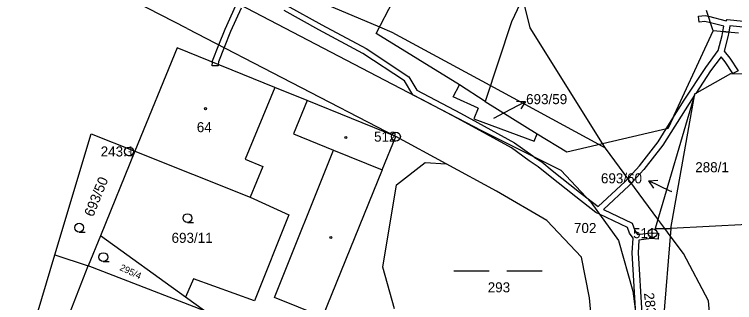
# Model space of a CAD drawing. Extents: x -747333 to -745433, y -1133152 to -1130600.
# Drawn here: x -746346.5 to -746224.7, y -1132134.3 to -1132085.5 of the extents above; entities that cross this region are included whole.
import ezdxf

# ---------------------------------------------------------------- set-up
doc = ezdxf.new("R2010")
doc.units = 0
for name, color, linetype in [('Vrstva 1', 7, 'Continuous'), ('Vrstva 16', 7, 'Continuous'), ('Vrstva 17', 7, 'Continuous'), ('Vrstva 18', 7, 'Continuous'), ('Vrstva 19', 7, 'Continuous'), ('Vrstva 24', 7, 'Continuous'), ('Vrstva 25', 7, 'Continuous'), ('Vrstva 3', 7, 'Continuous'), ('Vrstva 30', 7, 'Continuous'), ('Vrstva 37', 7, 'Continuous'), ('Vrstva 4', 7, 'Continuous'), ('Vrstva 52', 7, 'Continuous'), ('Vrstva 6', 7, 'Continuous')]:
    doc.layers.add(name, color=color, linetype=linetype)

msp = doc.modelspace()

# ---------------------------------------------------------------- linework, layer by layer
at = {"layer": 'Vrstva 1'}
msp.add_line((-746338.7, -1132140.02), (-746334.03, -1132128.06), dxfattribs=at)
for points in [[(-746242.88, -1132045.31), (-746262.42, -1132086.72)], [(-746317.29, -1132087.85), (-746364.32, -1132063.67)], [(-746282.49, -1132097.32), (-746324.12, -1132075.54)], [(-746285.29, -1132088.71), (-746282.45, -1132083.18)], [(-746228.31, -1132088.24), (-746229.39, -1132084.77)], [(-746262.42, -1132086.72), (-746266.88, -1132100.2)], [(-746317.29, -1132087.85), (-746281.98, -1132106.18)], [(-746271.22, -1132097.41), (-746285.29, -1132088.71)], [(-746235.88, -1132104.76), (-746228.31, -1132088.24)], [(-746223.98, -1132088.61), (-746228.31, -1132088.24)], [(-746318.98, -1132091.11), (-746326.13, -1132108.66)], [(-746302.49, -1132097.83), (-746318.98, -1132091.11)], [(-746231.38, -1132098.93), (-746225.32, -1132095.47)], [(-746225.32, -1132095.47), (-746214.11, -1132095.55)], [(-746296.99, -1132100.07), (-746302.49, -1132097.83)], [(-746267.43, -1132105.17), (-746282.49, -1132097.32)], [(-746266.88, -1132100.2), (-746271.22, -1132097.41)], [(-746235.45, -1132121.74), (-746231.38, -1132098.93)], [(-746281.98, -1132106.18), (-746296.99, -1132100.07)], [(-746266.88, -1132100.2), (-746258.07, -1132105.71)], [(-746254.03, -1132111.91), (-746267.43, -1132105.17)], [(-746253.04, -1132108.76), (-746235.88, -1132104.76)], [(-746339.72, -1132126.2), (-746333.57, -1132105.7), (-746326.13, -1132108.66)], [(-746284.28, -1132111.82), (-746281.98, -1132106.18)], [(-746273.47, -1132110.79), (-746281.98, -1132106.18)], [(-746258.07, -1132105.71), (-746253.04, -1132108.76)], [(-746326.13, -1132108.66), (-746331.96, -1132122.97)], [(-746326.13, -1132108.66), (-746306.63, -1132116.44)], [(-746281.86, -1132114.35), (-746277.01, -1132110.58)], [(-746277.01, -1132110.58), (-746273.47, -1132110.79)], [(-746264.93, -1132115.42), (-746273.47, -1132110.79)], [(-746284.28, -1132111.82), (-746294.42, -1132136.7)], [(-746248.97, -1132117.3), (-746254.03, -1132111.91)], [(-746284.17, -1132128.28), (-746281.86, -1132114.35)], [(-746256.46, -1132120.37), (-746264.93, -1132115.42)], [(-746306.63, -1132116.44), (-746300.07, -1132119.44)], [(-746248.97, -1132117.3), (-746244.31, -1132123.79)], [(-746300.07, -1132119.44), (-746305.92, -1132134.02)], [(-746250.55, -1132126.59), (-746256.46, -1132120.37)], [(-746209.52, -1132120.42), (-746235.45, -1132121.74)], [(-746235.45, -1132121.74), (-746236.75, -1132137.7)], [(-746331.96, -1132122.97), (-746334.03, -1132128.06)], [(-746317.6, -1132133.4), (-746331.96, -1132122.97)], [(-746244.31, -1132123.79), (-746241.88, -1132132.35)], [(-746345.51, -1132156.33), (-746348.32, -1132155.23), (-746339.72, -1132126.2)], [(-746339.72, -1132126.2), (-746334.03, -1132128.06)], [(-746249.24, -1132133.5), (-746250.55, -1132126.59)], [(-746314.39, -1132135.73), (-746334.03, -1132128.06)], [(-746282.24, -1132135.36), (-746284.17, -1132128.28)], [(-746316.23, -1132130.3), (-746317.6, -1132133.4)], [(-746305.92, -1132134.02), (-746316.23, -1132130.3)], [(-746241.88, -1132132.35), (-746241.11, -1132138.34)], [(-746314.39, -1132135.73), (-746317.6, -1132133.4)], [(-746248.4, -1132142.18), (-746249.24, -1132133.5)]]:
    msp.add_lwpolyline(points, dxfattribs=at)
at = {"layer": 'Vrstva 16'}
for p, q in [((-746261.552703, -1132100.145963), (-746260.05292, -1132100.202097)), ((-746238.323904, -1132114.891817), (-746239.159636, -1132113.645201))]:
    msp.add_line(p, q, dxfattribs=at)
for points in [[(-746263.59, -1132102.07), (-746260.05292, -1132100.202097), (-746260.852239, -1132101.472368)], [(-746265.39, -1132103.02), (-746263.59, -1132102.07)], [(-746235.57, -1132115.41), (-746239.159636, -1132113.645201), (-746237.662104, -1132113.545704)], [(-746235.27, -1132115.56), (-746235.57, -1132115.41)]]:
    msp.add_lwpolyline(points, dxfattribs=at)
at = {"layer": 'Vrstva 24'}
for p, q in [((-746282.03, -1132106.18), (-746281.93, -1132106.18)), ((-746327.18, -1132108.69), (-746327.08, -1132108.69)), ((-746238.56, -1132122.54), (-746238.46, -1132122.54))]:
    msp.add_line(p, q, dxfattribs=at)
for centre in [(-746281.98, -1132106.18), (-746327.13, -1132108.69), (-746238.51, -1132122.54)]:
    msp.add_circle(centre, 0.756017, dxfattribs=at)
at = {"layer": 'Vrstva 25'}
for p, q in [((-746317.25, -1132120.74), (-746316.25, -1132120.74)), ((-746335.58, -1132122.35), (-746334.58, -1132122.35)), ((-746331.49, -1132127.35), (-746330.49, -1132127.35)), ((-746272.2, -1132128.9), (-746266.2, -1132128.9)), ((-746263.2, -1132128.9), (-746257.2, -1132128.9))]:
    msp.add_line(p, q, dxfattribs=at)
for centre, radius in [((-746314.18, -1132101.43), 0.174503), ((-746290.45, -1132106.31), 0.174503), ((-746317.25, -1132119.99), 0.75), ((-746335.58, -1132121.6), 0.75), ((-746292.99, -1132123.29), 0.174503), ((-746331.49, -1132126.6), 0.75)]:
    msp.add_circle(centre, radius, dxfattribs=at)
at = {"layer": 'Vrstva 3'}
for points in [[(-746318.98, -1132091.11), (-746326.13, -1132108.66)], [(-746302.49, -1132097.83), (-746318.98, -1132091.11)], [(-746302.49, -1132097.83), (-746307.46, -1132110.02)], [(-746326.13, -1132108.66), (-746306.63, -1132116.44)], [(-746307.46, -1132110.02), (-746304.5, -1132111.22)], [(-746304.5, -1132111.22), (-746306.63, -1132116.44)]]:
    msp.add_lwpolyline(points, dxfattribs=at)
at = {"layer": 'Vrstva 30'}
for points in [[(-746310.87, -1132087.97), (-746309.08, -1132083.95)], [(-746308.18, -1132084.39), (-746309.95, -1132088.37)], [(-746300.41, -1132083.95), (-746294.53, -1132087.2)], [(-746295.01, -1132088.08), (-746300.91, -1132084.81)], [(-746230.77, -1132085.76), (-746229.63, -1132085.63)], [(-746229.63, -1132085.63), (-746229.08, -1132085.78)], [(-746230.66, -1132086.75), (-746230.77, -1132085.76)], [(-746229.71, -1132086.65), (-746230.66, -1132086.75)], [(-746228.73, -1132086.9), (-746229.71, -1132086.65)], [(-746229.08, -1132085.78), (-746226.06, -1132086.55)], [(-746226.48, -1132087.47), (-746228.73, -1132086.9)], [(-746226.06, -1132086.55), (-746225.9, -1132086.34)], [(-746225.9, -1132086.34), (-746223.13, -1132086.61)], [(-746311.94, -1132090.63), (-746310.87, -1132087.97)], [(-746287.55, -1132092.09), (-746295.01, -1132088.08)], [(-746294.53, -1132087.2), (-746287.03, -1132091.23)], [(-746226.66, -1132088.38), (-746226.48, -1132087.47)], [(-746225.45, -1132087.39), (-746225.66, -1132088.47)], [(-746223.21, -1132087.61), (-746225.45, -1132087.39)], [(-746309.95, -1132088.37), (-746311.05, -1132091.09)], [(-746227.45, -1132091.59), (-746226.79, -1132089.04)], [(-746226.79, -1132089.04), (-746226.66, -1132088.38)], [(-746226.66, -1132088.38), (-746225.66, -1132088.47)], [(-746225.66, -1132088.47), (-746226.66, -1132088.38)], [(-746225.81, -1132089.28), (-746226.44, -1132091.69)], [(-746225.66, -1132088.47), (-746225.81, -1132089.28)], [(-746313.01, -1132093.31), (-746311.94, -1132090.63)], [(-746311.05, -1132091.09), (-746312.02, -1132093.52)], [(-746287.03, -1132091.23), (-746279.78, -1132096.02)], [(-746229.55, -1132094.44), (-746227.45, -1132091.59)], [(-746226.44, -1132091.69), (-746225.45, -1132092.88)], [(-746280.52, -1132096.72), (-746287.55, -1132092.09)], [(-746226.96, -1132092.62), (-746228.73, -1132095.02)], [(-746226.25, -1132093.48), (-746226.96, -1132092.62)], [(-746225.45, -1132092.88), (-746224.06, -1132095.02)], [(-746313.05, -1132094.15), (-746313.02, -1132093.54)], [(-746312.05, -1132094.19), (-746313.05, -1132094.15)], [(-746313.02, -1132093.54), (-746313.01, -1132093.31)], [(-746312.04, -1132093.94), (-746312.05, -1132094.19)], [(-746312.02, -1132093.52), (-746312.04, -1132093.94)], [(-746224.95, -1132095.47), (-746226.25, -1132093.48)], [(-746233.2, -1132100.02), (-746229.55, -1132094.44)], [(-746228.73, -1132095.02), (-746231.24, -1132098.85)], [(-746224.06, -1132095.02), (-746224.95, -1132095.47)], [(-746279.78, -1132096.02), (-746278.43, -1132098.28)], [(-746279.13, -1132099.07), (-746280.52, -1132096.72)], [(-746276.39, -1132100.5), (-746279.13, -1132099.07)], [(-746278.43, -1132098.28), (-746271.05, -1132102.2)], [(-746231.38, -1132098.93), (-746231.45, -1132099.17)], [(-746231.24, -1132098.85), (-746231.38, -1132098.93)], [(-746235.09, -1132103.03), (-746233.2, -1132100.02)], [(-746231.45, -1132099.17), (-746232.36, -1132100.56)], [(-746271.52, -1132103.09), (-746276.39, -1132100.5)], [(-746232.36, -1132100.56), (-746236.8, -1132107.65)], [(-746271.05, -1132102.2), (-746261.9, -1132107.25)], [(-746262.44, -1132108.09), (-746271.52, -1132103.09)], [(-746236.22, -1132104.84), (-746235.09, -1132103.03), (-746235.88, -1132104.76), (-746236.22, -1132104.84)], [(-746235.88, -1132104.76), (-746235.09, -1132103.03)], [(-746237.62, -1132107.07), (-746236.22, -1132104.84)], [(-746236.22, -1132104.84), (-746235.88, -1132104.76)], [(-746261.9, -1132107.25), (-746258.83, -1132109.45)], [(-746240.76, -1132111.11), (-746237.62, -1132107.07)], [(-746236.8, -1132107.65), (-746240, -1132111.75)], [(-746259.41, -1132110.27), (-746262.44, -1132108.09)], [(-746258.83, -1132109.45), (-746258.56, -1132109.63)], [(-746258.56, -1132109.63), (-746257.3, -1132110.47)], [(-746257.9, -1132111.27), (-746259.41, -1132110.27)], [(-746256.13, -1132112.68), (-746257.9, -1132111.27)], [(-746257.3, -1132110.47), (-746255.51, -1132111.9)], [(-746243.2, -1132113.77), (-746240.76, -1132111.11)], [(-746255.51, -1132111.9), (-746250.89, -1132115.59)], [(-746240, -1132111.75), (-746242.5, -1132114.47)], [(-746251.51, -1132116.37), (-746256.13, -1132112.68)], [(-746247.77, -1132118.04), (-746243.2, -1132113.77)], [(-746242.5, -1132114.47), (-746246.84, -1132118.55)], [(-746250.89, -1132115.59), (-746249.69, -1132116.53)], [(-746248.12, -1132119.05), (-746251.51, -1132116.37)], [(-746249.69, -1132116.53), (-746247.77, -1132118.04)], [(-746246.84, -1132118.55), (-746241.98, -1132120.86)], [(-746247.51, -1132119.34), (-746248.12, -1132119.05)], [(-746242.78, -1132121.58), (-746247.51, -1132119.34)], [(-746241.98, -1132120.86), (-746241.53, -1132122.07)], [(-746242.43, -1132122.52), (-746242.78, -1132121.58)], [(-746241.53, -1132122.07), (-746241.08, -1132122.75)], [(-746241.84, -1132123.41), (-746242.43, -1132122.52)], [(-746242, -1132125.85), (-746241.84, -1132123.41)], [(-746241.08, -1132122.75), (-746238.8, -1132122.46)], [(-746238.77, -1132123.46), (-746240.86, -1132123.72)], [(-746238.8, -1132122.46), (-746237.53, -1132122.53)], [(-746237.59, -1132123.53), (-746238.77, -1132123.46)], [(-746237.53, -1132122.53), (-746237.59, -1132123.53)], [(-746240.86, -1132123.72), (-746241, -1132125.85)], [(-746241.37, -1132136.3), (-746242, -1132125.85)], [(-746241, -1132125.85), (-746240.38, -1132136.16)]]:
    msp.add_lwpolyline(points, dxfattribs=at)
at = {"layer": 'Vrstva 37'}
msp.add_circle((-746314.18, -1132101.43), 0.174503, dxfattribs=at)
at = {"layer": 'Vrstva 4'}
for points in [[(-746302.49, -1132097.83), (-746307.46, -1132110.02)], [(-746296.99, -1132100.07), (-746299.29, -1132105.7)], [(-746299.29, -1132105.7), (-746292.53, -1132108.46)], [(-746302.51, -1132133.44), (-746292.53, -1132108.46)], [(-746292.53, -1132108.46), (-746284.28, -1132111.82)], [(-746307.46, -1132110.02), (-746304.5, -1132111.22)], [(-746304.5, -1132111.22), (-746306.63, -1132116.44)], [(-746294.42, -1132136.7), (-746302.51, -1132133.44)]]:
    msp.add_lwpolyline(points, dxfattribs=at)
at = {"layer": 'Vrstva 52'}
for points in [[(-746246.5, -1132108.12), (-746247.65, -1132107.5), (-746266, -1132097.53), (-746282.63, -1132088.5), (-746284.72, -1132087.61), (-746300.5, -1132080.87), (-746327.94, -1132073.42), (-746328.56, -1132073.25), (-746347.25, -1132069.88), (-746350.56, -1132070.74), (-746411.94, -1132086.88), (-746415.94, -1132087.47), (-746420.08, -1132088.64), (-746420.35, -1132088.38), (-746424.25, -1132089.37), (-746427.25, -1132089), (-746438.31, -1132090.25), (-746447.63, -1132090.8)], [(-746246.5, -1132108.12), (-746246.99, -1132107.35), (-746259.25, -1132087.75), (-746260.5, -1132082.64)], [(-746228.83, -1132136.68), (-746229.06, -1132134), (-746233.31, -1132126), (-746235.55, -1132122.97), (-746236.45, -1132121.75), (-746237.64, -1132120.14), (-746246.5, -1132108.12)]]:
    msp.add_lwpolyline(points, dxfattribs=at)
at = {"layer": 'Vrstva 6'}
for points in [[(-746272.31, -1132099.42), (-746271.22, -1132097.41)], [(-746231.38, -1132098.93), (-746238.12, -1132121.77)], [(-746268.04, -1132101.35), (-746272.31, -1132099.42)], [(-746268.04, -1132101.35), (-746268.77, -1132103.18)], [(-746268.77, -1132103.18), (-746258.56, -1132106.96)], [(-746258.56, -1132106.96), (-746258.07, -1132105.71)], [(-746238.12, -1132121.77), (-746235.45, -1132121.74)]]:
    msp.add_lwpolyline(points, dxfattribs=at)

# ---------------------------------------------------------------- texts
at = {"layer": 'Vrstva 16'}
for s, p in [('693/59', (-746259.94, -1132100.67)), ('693/60', (-746247.278921, -1132114.09))]:
    msp.add_text(s, height=1.7, dxfattribs=at).set_placement(p)
msp.add_text('283/3', height=1.7, rotation=276.42222, dxfattribs=at).set_placement((-746240.002027, -1132132.714285))
at = {"layer": 'Vrstva 17'}
for s, p in [('512', (-746285.670721, -1132107.03)), ('243.1', (-746331.934603, -1132109.54)), ('511', (-746241.84163, -1132123.39))]:
    msp.add_text(s, height=1.7, dxfattribs=at).set_placement(p)
at = {"layer": 'Vrstva 18'}
for s, height, p in [('693/59', 0.1, (-746265.39, -1132103.02)), ('288/1', 1.7, (-746231.32, -1132112.21)), ('702', 1.7, (-746251.84, -1132122.51)), ('693/11', 1.7, (-746319.94, -1132124.18)), ('293', 1.7, (-746266.44, -1132132.57))]:
    msp.add_text(s, height=height, dxfattribs=at).set_placement(p)
for s, height, rotation, p in [('693/50', 1.7, 68.02002, (-746333.215217, -1132119.889742)), ('693/60', 0.1, 79.37325, (-746235.27, -1132115.56)), ('295/4', 1.14, 334.62846, (-746328.832056, -1132128.753768))]:
    msp.add_text(s, height=height, rotation=rotation, dxfattribs=at).set_placement(p)
at = {"layer": 'Vrstva 19'}
msp.add_text('64', height=1.7, dxfattribs=at).set_placement((-746315.67, -1132105.42))

doc.saveas('drawing.dxf')
